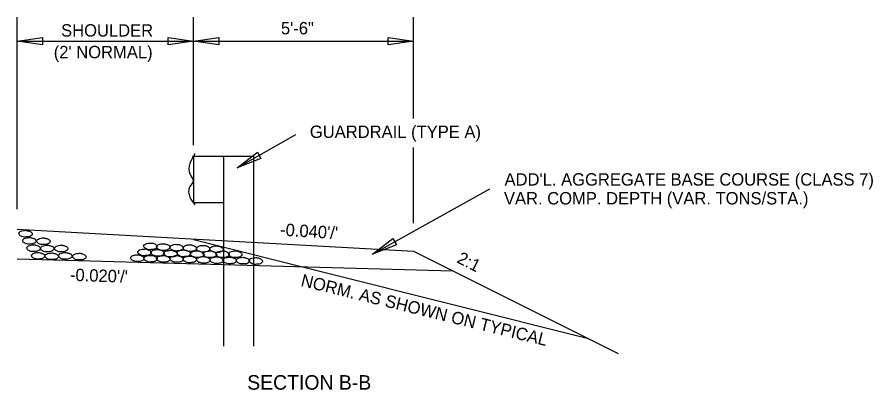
# Model space of a CAD drawing. Extents: x -149 to 1228740, y -106 to 152440.
# Drawn here: x -149.4 to -90.4, y -42.2 to -16.6 of the extents above; entities that cross this region are included whole.
import ezdxf

# ---------------------------------------------------------------- set-up
doc = ezdxf.new("R2010")
doc.units = 0
for name, color, linetype in [('R_Annotation', 7, 'Continuous'), ('R_Dimension', 7, 'Continuous'), ('R_Proposed Road', 7, 'Continuous'), ('R_Proposed Road_Lane', 7, 'Continuous'), ('R_Proposed Road_Shoulder', 7, 'Continuous')]:
    doc.layers.add(name, color=color, linetype=linetype)

msp = doc.modelspace()

# ---------------------------------------------------------------- linework, layer by layer
at = {"layer": 'R_Dimension'}
for p, q in [((-149.389, -29.791), (-149.389, -16.561)), ((-137.238, -25.394), (-137.238, -16.564)), ((-122.084, -23.554), (-122.084, -16.564)), ((-149.383, -18.222), (-137.238, -18.222)), ((-137.238, -18.222), (-122.084, -18.222)), ((-134.235, -26.94), (-130.19, -24.65)), ((-122.084, -30.758), (-122.084, -25.549)), ((-124.897, -32.901), (-116.821, -28.393))]:
    msp.add_line(p, q, dxfattribs=at)
for points in [[(-147.633, -18.472), (-149.383, -18.222), (-147.633, -17.972)], [(-138.981, -17.974), (-137.231, -18.224), (-138.981, -18.474)], [(-135.481, -18.474), (-137.231, -18.224), (-135.481, -17.974)], [(-123.826, -17.974), (-122.076, -18.224), (-123.826, -18.474)], [(-132.589, -26.295), (-134.235, -26.94), (-132.835, -25.86)], [(-123.251, -32.256), (-124.897, -32.901), (-123.497, -31.821)]]:
    msp.add_lwpolyline(points, close=True, dxfattribs=at)
at = {"layer": 'R_Proposed Road'}
msp.add_line((-149.383, -33.219), (-119.375, -34.041), dxfattribs=at)
for points in [[(-148.81, -31.251), (-148.972, -31.271), (-149.159, -31.33), (-149.252, -31.414), (-149.267, -31.473), (-149.223, -31.571), (-149.169, -31.62), (-149.06, -31.679), (-148.903, -31.713), (-148.825, -31.713), (-148.702, -31.708), (-148.569, -31.694), (-148.461, -31.649), (-148.363, -31.561), (-148.348, -31.502), (-148.378, -31.414), (-148.451, -31.355), (-148.525, -31.32), (-148.633, -31.286), (-148.707, -31.266), (-148.81, -31.251)], [(-148.543, -31.739), (-148.705, -31.759), (-148.892, -31.818), (-148.99, -31.902), (-149.005, -31.96), (-148.961, -32.059), (-148.907, -32.108), (-148.798, -32.167), (-148.641, -32.201), (-148.558, -32.201), (-148.435, -32.196), (-148.302, -32.182), (-148.199, -32.137), (-148.096, -32.049), (-148.081, -31.99), (-148.111, -31.902), (-148.184, -31.843), (-148.258, -31.808), (-148.371, -31.774), (-148.44, -31.754), (-148.543, -31.739)], [(-147.579, -31.771), (-147.741, -31.791), (-147.927, -31.85), (-148.026, -31.933), (-148.04, -31.992), (-147.996, -32.091), (-147.942, -32.14), (-147.834, -32.199), (-147.677, -32.233), (-147.593, -32.233), (-147.471, -32.228), (-147.338, -32.213), (-147.235, -32.169), (-147.132, -32.081), (-147.117, -32.022), (-147.146, -31.933), (-147.22, -31.874), (-147.294, -31.84), (-147.407, -31.806), (-147.475, -31.786), (-147.579, -31.771)], [(-148.257, -32.25), (-148.419, -32.27), (-148.606, -32.329), (-148.704, -32.412), (-148.719, -32.466), (-148.675, -32.565), (-148.621, -32.619), (-148.513, -32.678), (-148.356, -32.712), (-148.272, -32.712), (-148.149, -32.707), (-148.017, -32.692), (-147.913, -32.643), (-147.81, -32.56), (-147.796, -32.496), (-147.825, -32.407), (-147.899, -32.349), (-147.972, -32.314), (-148.085, -32.285), (-148.154, -32.26), (-148.257, -32.25)], [(-147.308, -32.272), (-147.47, -32.292), (-147.656, -32.351), (-147.755, -32.434), (-147.769, -32.489), (-147.725, -32.587), (-147.671, -32.641), (-147.563, -32.7), (-147.406, -32.734), (-147.322, -32.734), (-147.2, -32.729), (-147.067, -32.714), (-146.964, -32.665), (-146.861, -32.582), (-146.846, -32.518), (-146.875, -32.43), (-146.949, -32.371), (-147.023, -32.336), (-147.136, -32.307), (-147.204, -32.282), (-147.308, -32.272)], [(-146.351, -32.271), (-146.513, -32.29), (-146.7, -32.349), (-146.793, -32.433), (-146.808, -32.487), (-146.764, -32.585), (-146.71, -32.639), (-146.602, -32.698), (-146.445, -32.733), (-146.366, -32.733), (-146.243, -32.728), (-146.111, -32.713), (-146.003, -32.664), (-145.904, -32.58), (-145.89, -32.516), (-145.919, -32.428), (-145.993, -32.369), (-146.066, -32.335), (-146.175, -32.305), (-146.248, -32.281), (-146.351, -32.271)], [(-140.19, -32.127), (-140.353, -32.137), (-140.549, -32.196), (-140.652, -32.29), (-140.667, -32.344), (-140.618, -32.442), (-140.559, -32.486), (-140.446, -32.54), (-140.289, -32.584), (-140.205, -32.584), (-140.087, -32.574), (-139.955, -32.56), (-139.851, -32.52), (-139.763, -32.437), (-139.748, -32.373), (-139.778, -32.285), (-139.842, -32.226), (-139.91, -32.186), (-140.018, -32.142), (-140.087, -32.127), (-140.19, -32.127)], [(-139.31, -32.18), (-139.472, -32.19), (-139.664, -32.258), (-139.762, -32.337), (-139.777, -32.391), (-139.723, -32.494), (-139.679, -32.548), (-139.561, -32.597), (-139.413, -32.632), (-139.33, -32.642), (-139.207, -32.637), (-139.07, -32.612), (-138.971, -32.568), (-138.868, -32.489), (-138.853, -32.425), (-138.883, -32.337), (-138.957, -32.273), (-139.03, -32.239), (-139.138, -32.204), (-139.207, -32.19), (-139.31, -32.18)], [(-138.394, -32.217), (-138.556, -32.222), (-138.753, -32.29), (-138.851, -32.379), (-138.866, -32.438), (-138.812, -32.536), (-138.758, -32.58), (-138.65, -32.629), (-138.492, -32.673), (-138.409, -32.678), (-138.291, -32.669), (-138.158, -32.644), (-138.055, -32.605), (-137.957, -32.526), (-137.942, -32.467), (-137.972, -32.379), (-138.045, -32.32), (-138.114, -32.271), (-138.222, -32.236), (-138.291, -32.222), (-138.394, -32.217)], [(-137.478, -32.253), (-137.64, -32.258), (-137.837, -32.327), (-137.935, -32.416), (-137.95, -32.475), (-137.896, -32.573), (-137.842, -32.617), (-137.733, -32.666), (-137.576, -32.71), (-137.493, -32.715), (-137.375, -32.705), (-137.242, -32.681), (-137.139, -32.642), (-137.041, -32.563), (-137.026, -32.504), (-137.056, -32.416), (-137.129, -32.357), (-137.198, -32.308), (-137.306, -32.273), (-137.375, -32.258), (-137.478, -32.253)], [(-136.562, -32.29), (-136.724, -32.295), (-136.92, -32.364), (-137.019, -32.452), (-137.033, -32.511), (-136.979, -32.61), (-136.925, -32.654), (-136.817, -32.703), (-136.66, -32.747), (-136.577, -32.752), (-136.459, -32.742), (-136.326, -32.718), (-136.223, -32.678), (-136.125, -32.6), (-136.11, -32.541), (-136.139, -32.452), (-136.213, -32.393), (-136.282, -32.344), (-136.39, -32.31), (-136.459, -32.295), (-136.562, -32.29)], [(-135.646, -32.327), (-135.808, -32.332), (-136.004, -32.401), (-136.103, -32.489), (-136.117, -32.548), (-136.063, -32.646), (-136.009, -32.691), (-135.901, -32.74), (-135.744, -32.784), (-135.66, -32.789), (-135.543, -32.779), (-135.41, -32.755), (-135.307, -32.715), (-135.209, -32.637), (-135.194, -32.578), (-135.223, -32.489), (-135.297, -32.43), (-135.366, -32.381), (-135.474, -32.347), (-135.543, -32.332), (-135.646, -32.327)], [(-147.942, -32.771), (-148.104, -32.791), (-148.291, -32.85), (-148.384, -32.933), (-148.399, -32.992), (-148.355, -33.09), (-148.301, -33.139), (-148.193, -33.198), (-148.035, -33.233), (-147.957, -33.233), (-147.834, -33.228), (-147.701, -33.213), (-147.593, -33.169), (-147.495, -33.08), (-147.48, -33.022), (-147.51, -32.933), (-147.584, -32.874), (-147.657, -32.84), (-147.765, -32.805), (-147.839, -32.786), (-147.942, -32.771)], [(-147.004, -32.807), (-147.166, -32.827), (-147.353, -32.886), (-147.446, -32.969), (-147.461, -33.028), (-147.417, -33.126), (-147.362, -33.175), (-147.254, -33.234), (-147.097, -33.269), (-147.019, -33.269), (-146.896, -33.264), (-146.763, -33.249), (-146.655, -33.205), (-146.557, -33.116), (-146.542, -33.058), (-146.572, -32.969), (-146.645, -32.91), (-146.719, -32.876), (-146.827, -32.841), (-146.901, -32.822), (-147.004, -32.807)], [(-146.068, -32.781), (-146.23, -32.8), (-146.417, -32.859), (-146.51, -32.943), (-146.525, -32.997), (-146.481, -33.095), (-146.427, -33.149), (-146.319, -33.208), (-146.161, -33.243), (-146.083, -33.243), (-145.96, -33.238), (-145.827, -33.223), (-145.719, -33.174), (-145.621, -33.09), (-145.606, -33.026), (-145.636, -32.938), (-145.709, -32.879), (-145.783, -32.845), (-145.891, -32.815), (-145.965, -32.791), (-146.068, -32.781)], [(-145.105, -32.832), (-145.267, -32.851), (-145.454, -32.91), (-145.547, -32.994), (-145.562, -33.048), (-145.518, -33.146), (-145.464, -33.2), (-145.356, -33.259), (-145.199, -33.293), (-145.12, -33.293), (-144.997, -33.288), (-144.865, -33.274), (-144.757, -33.225), (-144.658, -33.141), (-144.644, -33.077), (-144.673, -32.989), (-144.747, -32.93), (-144.82, -32.895), (-144.928, -32.866), (-145.002, -32.841), (-145.105, -32.832)], [(-141.098, -32.946), (-141.26, -32.951), (-141.457, -33.02), (-141.55, -33.108), (-141.565, -33.167), (-141.516, -33.265), (-141.457, -33.31), (-141.354, -33.359), (-141.192, -33.403), (-141.113, -33.408), (-140.99, -33.398), (-140.858, -33.373), (-140.755, -33.334), (-140.661, -33.256), (-140.646, -33.197), (-140.676, -33.108), (-140.75, -33.049), (-140.818, -33), (-140.926, -32.966), (-140.995, -32.951), (-141.098, -32.946)], [(-140.597, -32.538), (-140.769, -32.557), (-140.961, -32.606), (-141.059, -32.7), (-141.074, -32.754), (-141.025, -32.857), (-140.966, -32.901), (-140.858, -32.96), (-140.7, -32.999), (-140.622, -32.999), (-140.499, -32.99), (-140.362, -32.98), (-140.258, -32.931), (-140.17, -32.847), (-140.155, -32.783), (-140.185, -32.695), (-140.258, -32.636), (-140.327, -32.606), (-140.435, -32.562), (-140.499, -32.542), (-140.597, -32.538)], [(-140.19, -32.975), (-140.352, -32.99), (-140.548, -33.048), (-140.642, -33.137), (-140.656, -33.196), (-140.607, -33.294), (-140.558, -33.338), (-140.445, -33.387), (-140.293, -33.437), (-140.209, -33.437), (-140.086, -33.427), (-139.949, -33.407), (-139.851, -33.373), (-139.752, -33.284), (-139.738, -33.225), (-139.767, -33.137), (-139.841, -33.078), (-139.915, -33.034), (-140.018, -32.994), (-140.086, -32.98), (-140.19, -32.975)], [(-139.706, -32.579), (-139.868, -32.584), (-140.064, -32.648), (-140.163, -32.741), (-140.177, -32.795), (-140.123, -32.899), (-140.069, -32.943), (-139.961, -32.992), (-139.804, -33.031), (-139.72, -33.041), (-139.603, -33.031), (-139.47, -33.007), (-139.367, -32.967), (-139.269, -32.889), (-139.254, -32.825), (-139.283, -32.737), (-139.357, -32.678), (-139.426, -32.633), (-139.534, -32.599), (-139.603, -32.584), (-139.706, -32.579)], [(-139.306, -32.988), (-139.468, -33.008), (-139.665, -33.062), (-139.763, -33.15), (-139.778, -33.209), (-139.724, -33.307), (-139.67, -33.351), (-139.562, -33.41), (-139.409, -33.45), (-139.326, -33.45), (-139.203, -33.44), (-139.07, -33.43), (-138.967, -33.386), (-138.869, -33.297), (-138.854, -33.238), (-138.884, -33.15), (-138.957, -33.091), (-139.031, -33.057), (-139.139, -33.017), (-139.203, -32.993), (-139.306, -32.988)], [(-138.798, -32.629), (-138.96, -32.644), (-139.156, -32.698), (-139.26, -32.791), (-139.274, -32.845), (-139.22, -32.944), (-139.166, -32.988), (-139.053, -33.052), (-138.901, -33.086), (-138.817, -33.086), (-138.7, -33.076), (-138.557, -33.071), (-138.459, -33.022), (-138.366, -32.939), (-138.351, -32.875), (-138.38, -32.786), (-138.449, -32.728), (-138.523, -32.693), (-138.626, -32.659), (-138.695, -32.629), (-138.798, -32.629)], [(-138.382, -32.987), (-138.549, -33.007), (-138.745, -33.061), (-138.844, -33.149), (-138.858, -33.208), (-138.804, -33.306), (-138.75, -33.351), (-138.637, -33.414), (-138.485, -33.449), (-138.406, -33.449), (-138.284, -33.444), (-138.146, -33.429), (-138.043, -33.385), (-137.95, -33.297), (-137.935, -33.238), (-137.964, -33.149), (-138.038, -33.09), (-138.112, -33.056), (-138.215, -33.021), (-138.279, -33.002), (-138.382, -32.987)], [(-137.904, -32.606), (-138.066, -32.626), (-138.257, -32.675), (-138.356, -32.768), (-138.37, -32.822), (-138.316, -32.926), (-138.262, -32.97), (-138.154, -33.029), (-137.997, -33.068), (-137.918, -33.068), (-137.796, -33.058), (-137.663, -33.048), (-137.555, -32.999), (-137.462, -32.916), (-137.447, -32.852), (-137.476, -32.764), (-137.55, -32.705), (-137.624, -32.675), (-137.727, -32.626), (-137.801, -32.611), (-137.904, -32.606)], [(-137.476, -33.024), (-137.648, -33.044), (-137.835, -33.093), (-137.938, -33.186), (-137.953, -33.24), (-137.899, -33.343), (-137.845, -33.387), (-137.732, -33.446), (-137.58, -33.486), (-137.501, -33.486), (-137.378, -33.476), (-137.236, -33.466), (-137.137, -33.417), (-137.044, -33.333), (-137.029, -33.27), (-137.059, -33.181), (-137.133, -33.122), (-137.201, -33.093), (-137.309, -33.053), (-137.373, -33.029), (-137.476, -33.024)], [(-136.975, -32.67), (-137.137, -32.675), (-137.334, -32.739), (-137.432, -32.832), (-137.447, -32.886), (-137.393, -32.99), (-137.339, -33.034), (-137.231, -33.083), (-137.074, -33.122), (-136.99, -33.132), (-136.872, -33.122), (-136.74, -33.098), (-136.636, -33.058), (-136.538, -32.98), (-136.523, -32.916), (-136.553, -32.827), (-136.627, -32.768), (-136.695, -32.724), (-136.803, -32.69), (-136.872, -32.675), (-136.975, -32.67)], [(-136.1, -32.67), (-136.262, -32.69), (-136.454, -32.739), (-136.552, -32.832), (-136.567, -32.886), (-136.513, -32.99), (-136.459, -33.034), (-136.351, -33.093), (-136.193, -33.132), (-136.115, -33.132), (-135.992, -33.122), (-135.859, -33.112), (-135.751, -33.063), (-135.658, -32.98), (-135.643, -32.916), (-135.673, -32.827), (-135.746, -32.768), (-135.82, -32.739), (-135.923, -32.69), (-135.997, -32.675), (-136.1, -32.67)], [(-135.225, -32.67), (-135.387, -32.69), (-135.579, -32.739), (-135.677, -32.832), (-135.692, -32.886), (-135.638, -32.99), (-135.584, -33.034), (-135.475, -33.093), (-135.318, -33.132), (-135.24, -33.132), (-135.117, -33.122), (-134.984, -33.112), (-134.876, -33.063), (-134.783, -32.98), (-134.768, -32.916), (-134.798, -32.827), (-134.871, -32.768), (-134.945, -32.739), (-135.048, -32.69), (-135.122, -32.675), (-135.225, -32.67)], [(-134.35, -32.67), (-134.512, -32.69), (-134.703, -32.739), (-134.802, -32.832), (-134.816, -32.886), (-134.762, -32.99), (-134.708, -33.034), (-134.6, -33.093), (-134.443, -33.132), (-134.364, -33.132), (-134.242, -33.122), (-134.109, -33.112), (-134.001, -33.063), (-133.908, -32.98), (-133.893, -32.916), (-133.922, -32.827), (-133.996, -32.768), (-134.07, -32.739), (-134.173, -32.69), (-134.247, -32.675), (-134.35, -32.67)], [(-136.55, -33.062), (-136.713, -33.071), (-136.904, -33.14), (-137.002, -33.219), (-137.017, -33.273), (-136.963, -33.376), (-136.919, -33.43), (-136.801, -33.479), (-136.654, -33.513), (-136.57, -33.523), (-136.447, -33.518), (-136.31, -33.494), (-136.211, -33.45), (-136.108, -33.371), (-136.094, -33.307), (-136.123, -33.219), (-136.197, -33.155), (-136.27, -33.12), (-136.379, -33.086), (-136.447, -33.071), (-136.55, -33.062)], [(-135.627, -33.08), (-135.789, -33.095), (-135.986, -33.154), (-136.079, -33.242), (-136.094, -33.301), (-136.044, -33.4), (-135.995, -33.444), (-135.882, -33.493), (-135.73, -33.542), (-135.647, -33.542), (-135.524, -33.532), (-135.386, -33.513), (-135.288, -33.478), (-135.19, -33.39), (-135.175, -33.331), (-135.204, -33.242), (-135.278, -33.184), (-135.352, -33.139), (-135.455, -33.1), (-135.524, -33.085), (-135.627, -33.08)], [(-134.73, -33.095), (-134.893, -33.115), (-135.089, -33.169), (-135.187, -33.257), (-135.202, -33.316), (-135.148, -33.414), (-135.094, -33.459), (-134.986, -33.518), (-134.834, -33.557), (-134.75, -33.557), (-134.627, -33.547), (-134.495, -33.537), (-134.391, -33.493), (-134.293, -33.405), (-134.279, -33.346), (-134.308, -33.257), (-134.382, -33.198), (-134.455, -33.164), (-134.563, -33.125), (-134.627, -33.1), (-134.73, -33.095)], [(-133.821, -33.107), (-133.988, -33.127), (-134.184, -33.181), (-134.283, -33.27), (-134.297, -33.328), (-134.243, -33.427), (-134.189, -33.471), (-134.076, -33.535), (-133.924, -33.569), (-133.845, -33.569), (-133.723, -33.564), (-133.585, -33.55), (-133.482, -33.505), (-133.389, -33.417), (-133.374, -33.358), (-133.403, -33.27), (-133.477, -33.211), (-133.551, -33.176), (-133.654, -33.142), (-133.718, -33.122), (-133.821, -33.107)], [(-132.934, -33.133), (-133.106, -33.152), (-133.298, -33.202), (-133.396, -33.295), (-133.411, -33.349), (-133.357, -33.447), (-133.303, -33.491), (-133.195, -33.55), (-133.037, -33.595), (-132.959, -33.595), (-132.836, -33.58), (-132.698, -33.575), (-132.595, -33.526), (-132.502, -33.442), (-132.487, -33.378), (-132.517, -33.29), (-132.59, -33.231), (-132.664, -33.197), (-132.767, -33.157), (-132.836, -33.138), (-132.934, -33.133)]]:
    msp.add_spline(points, degree=3, dxfattribs=at)
at = {"layer": 'R_Proposed Road_Lane'}
for p, q in [((-149.389, -31.17), (-122.079, -32.689)), ((-122.079, -32.689), (-107.976, -39.741))]:
    msp.add_line(p, q, dxfattribs=at)
at = {"layer": 'R_Proposed Road_Shoulder'}
for p, q in [((-137.238, -26.144), (-137.238, -29.323)), ((-137.238, -26.144), (-133.105, -26.144)), ((-135.171, -26.144), (-135.171, -39.226)), ((-133.105, -26.144), (-133.105, -39.238)), ((-137.238, -29.323), (-135.171, -29.323)), ((-137.232, -31.894), (-110.107, -38.675))]:
    msp.add_line(p, q, dxfattribs=at)
msp.add_spline([(-137.152, -25.967), (-137.486, -26.657), (-137.486, -27.367), (-137.262, -27.848), (-137.486, -28.241), (-137.486, -28.966), (-137.132, -29.489)], degree=3, dxfattribs=at)

# ---------------------------------------------------------------- texts
at = {"layer": 'R_Annotation'}
for s, height, p in [('SHOULDER ', 0.8533, (-146.357, -17.902)), ('5\'-6"', 0.8533, (-131.209, -17.749)), ("(2' NORMAL)", 0.85327, (-146.865, -19.395)), ('GUARDRAIL (TYPE A)', 0.85327, (-129.216, -24.887)), ("ADD'L. AGGREGATE BASE COURSE (CLASS 7)", 0.85327, (-115.8, -28.17)), ('VAR. COMP. DEPTH (VAR. TONS/STA.)', 0.85327, (-115.841, -29.469)), ('SECTION B-B', 1, (-133.532, -42.23))]:
    msp.add_text(s, height=height, dxfattribs=at).set_placement(p)
for s, height, rotation, p in [("-0.040'/'", 0.8533, 356.40267, (-131.288, -31.61)), ('2:1', 0.8533, 333.41453, (-119.147, -33.448)), ("-0.020'/'", 0.8533, 358.0742, (-145.76, -34.731)), ('NORM. AS SHOWN ON TYPICAL', 0.85327, 346.22108, (-129.888, -35.076))]:
    msp.add_text(s, height=height, rotation=rotation, dxfattribs=at).set_placement(p)

doc.saveas('drawing.dxf')
